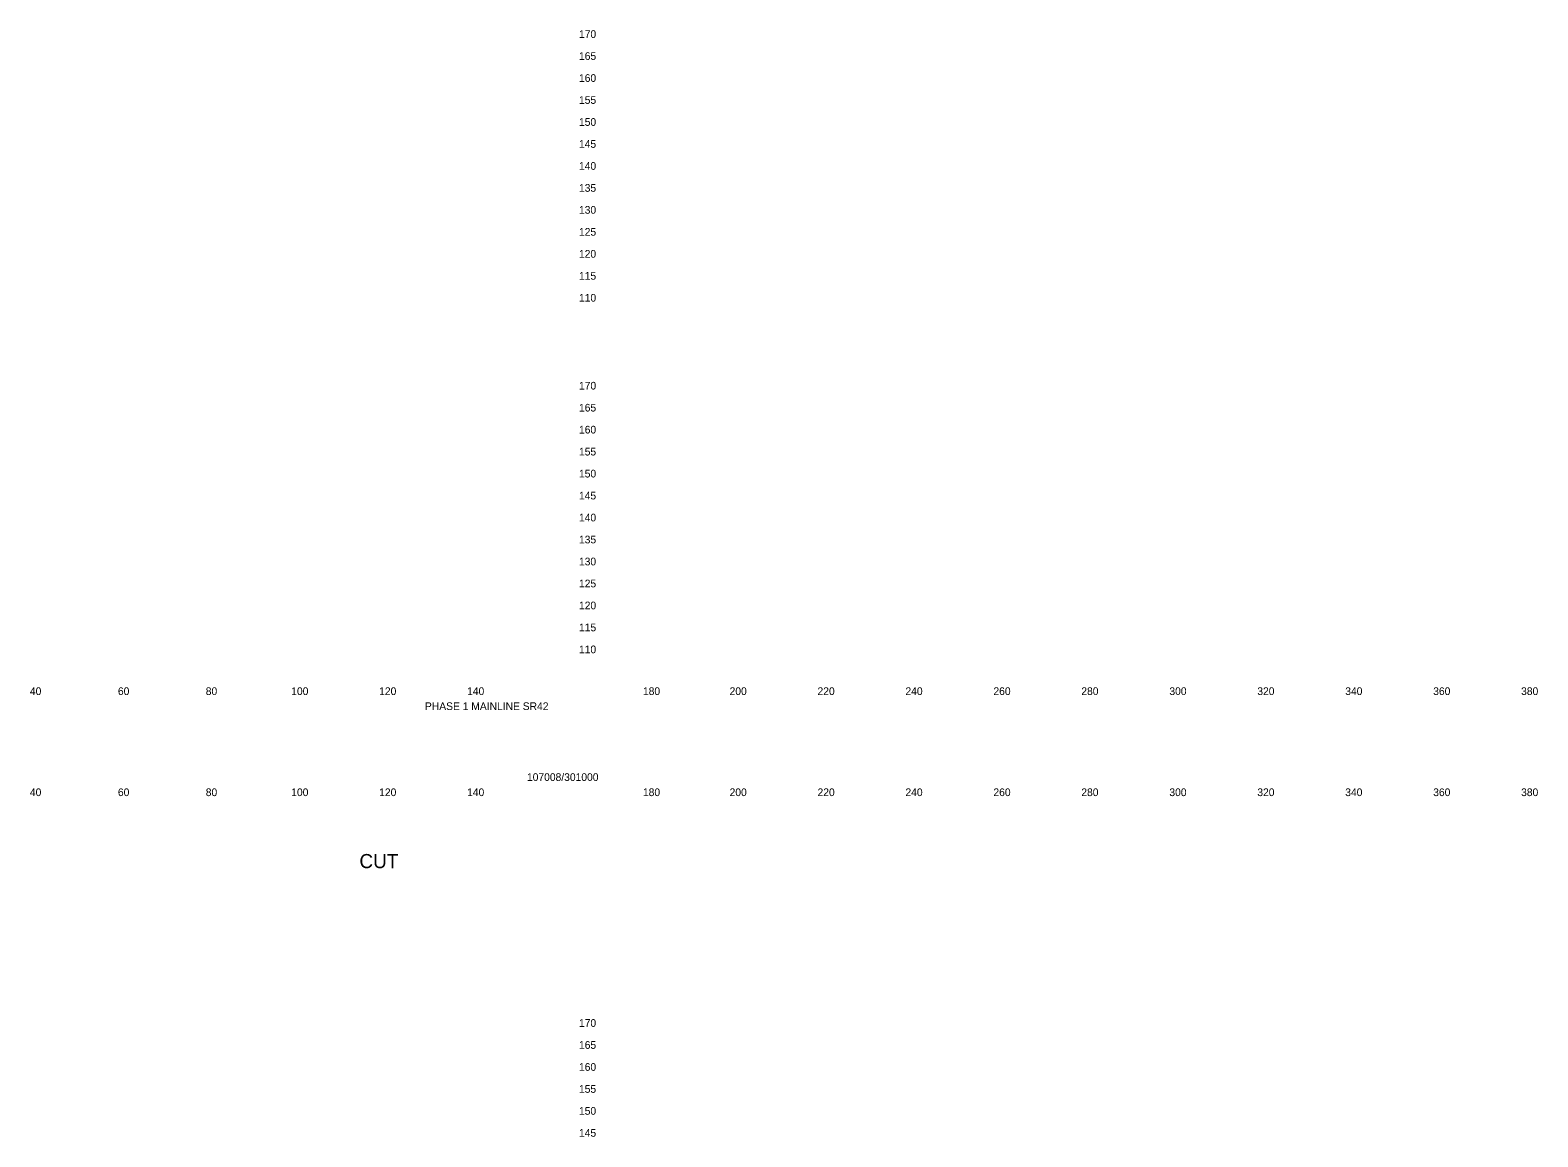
# Model space of a CAD drawing. Extents: x 21281 to 22024, y 6472 to 15198.
# Drawn here: x 21681.3 to 22024.2, y 10284.8 to 10536.6 of the extents above; entities that cross this region are included whole.
import ezdxf

# ---------------------------------------------------------------- set-up
doc = ezdxf.new("R2010")
doc.units = 0
doc.layers.add('XS_SHEET_LABELS_ELEVATION', color=7, linetype='Continuous')
doc.layers.add('XS_SHEET_LABELS_OFFSET', color=7, linetype='Continuous')

msp = doc.modelspace()

# ---------------------------------------------------------------- texts
at = {"layer": 'XS_SHEET_LABELS_ELEVATION'}
for s, p in [('  170  ', (21804.84, 10534.84)), ('  165  ', (21804.84, 10529.84)), ('  160  ', (21804.84, 10524.84)), ('  155  ', (21804.84, 10519.84)), ('  150  ', (21804.84, 10514.84)), ('  145  ', (21804.84, 10509.84)), ('  140  ', (21804.84, 10504.84)), ('  135  ', (21804.84, 10499.84)), ('  130  ', (21804.84, 10494.84)), ('  125  ', (21804.84, 10489.84)), ('  120  ', (21804.84, 10484.84)), ('  115  ', (21804.84, 10479.84)), ('  110  ', (21804.84, 10474.84)), ('  170  ', (21804.84, 10454.84)), ('  165  ', (21804.84, 10449.84)), ('  160  ', (21804.84, 10444.84)), ('  155  ', (21804.84, 10439.84)), ('  150  ', (21804.84, 10434.84)), ('  145  ', (21804.84, 10429.84)), ('  140  ', (21804.84, 10424.84)), ('  135  ', (21804.84, 10419.84)), ('  130  ', (21804.84, 10414.84)), ('  125  ', (21804.84, 10409.84)), ('  120  ', (21804.84, 10404.84)), ('  115  ', (21804.84, 10399.84)), ('  110  ', (21804.84, 10394.84)), ('  170  ', (21804.84, 10309.84)), ('  165  ', (21804.84, 10304.84)), ('  160  ', (21804.84, 10299.84)), ('  155  ', (21804.84, 10294.84)), ('  150  ', (21804.84, 10289.84)), ('  145  ', (21804.84, 10284.84))]:
    msp.add_text(s, height=1.75, dxfattribs=at).set_placement(p)
at = {"layer": 'XS_SHEET_LABELS_OFFSET'}
for s, height, p in [('  40  ', 1.75, (21679.95, 10385.34)), ('  60  ', 1.75, (21699.97, 10385.34)), ('  80  ', 1.75, (21719.95, 10385.34)), ('  100  ', 1.75, (21739.39, 10385.34)), ('  120  ', 1.75, (21759.39, 10385.34)), ('  140  ', 1.75, (21779.39, 10385.34)), ('  180  ', 1.75, (21819.39, 10385.34)), ('  200  ', 1.75, (21839.1, 10385.34)), ('  220  ', 1.75, (21859.1, 10385.34)), ('  240  ', 1.75, (21879.1, 10385.34)), ('  260  ', 1.75, (21899.11, 10385.34)), ('  280  ', 1.75, (21919.1, 10385.34)), ('  300  ', 1.75, (21939.13, 10385.34)), ('  320  ', 1.75, (21959.13, 10385.34)), ('  340  ', 1.75, (21979.13, 10385.34)), ('  360  ', 1.75, (21999.14, 10385.34)), ('  380  ', 1.75, (22019.13, 10385.34)), ('PHASE 1 MAINLINE SR42', 1.75, (21771.11, 10381.92)), ('107008/301000', 1.75, (21794.31, 10365.79)), ('  40  ', 1.75, (21679.95, 10362.34)), ('  60  ', 1.75, (21699.97, 10362.34)), ('  80  ', 1.75, (21719.95, 10362.34)), ('  100  ', 1.75, (21739.39, 10362.34)), ('  120  ', 1.75, (21759.39, 10362.34)), ('  140  ', 1.75, (21779.39, 10362.34)), ('  180  ', 1.75, (21819.39, 10362.34)), ('  200  ', 1.75, (21839.1, 10362.34)), ('  220  ', 1.75, (21859.1, 10362.34)), ('  240  ', 1.75, (21879.1, 10362.34)), ('  260  ', 1.75, (21899.11, 10362.34)), ('  280  ', 1.75, (21919.1, 10362.34)), ('  300  ', 1.75, (21939.13, 10362.34)), ('  320  ', 1.75, (21959.13, 10362.34)), ('  340  ', 1.75, (21979.13, 10362.34)), ('  360  ', 1.75, (21999.14, 10362.34)), ('  380  ', 1.75, (22019.13, 10362.34)), ('CUT', 3.222, (21756.2, 10345.94))]:
    msp.add_text(s, height=height, dxfattribs=at).set_placement(p)

doc.saveas('drawing.dxf')
